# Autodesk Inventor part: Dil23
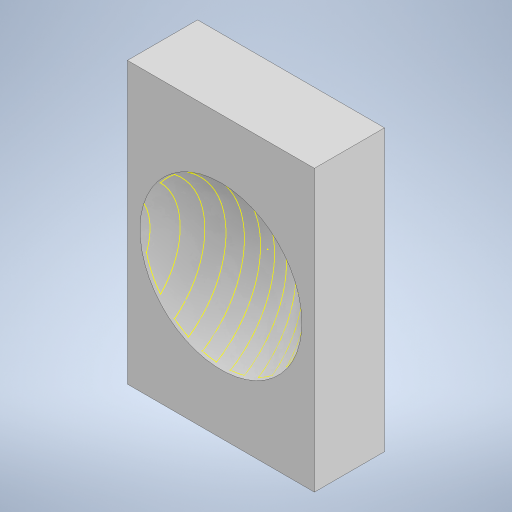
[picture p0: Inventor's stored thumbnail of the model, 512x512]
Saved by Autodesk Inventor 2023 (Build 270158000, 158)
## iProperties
Created: 2023-08
Part Number: Dil23
Material: Všeobecné
Document SubType Name: Modeling
Designer: KSR-Student_2
Density: 1 g/cm^3
Appearance: Výchozí
Author: KSR-Student_2
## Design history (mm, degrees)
sketch "Náčrt1"
  geometry: L1 (0, 0)-(400, 0); L2 (400, 0)-(400, -600); L3 (400, -600)-(0, -600); L4 (0, -600)-(0, 0)
  constraints: 8 end point, 2 parallel, 1 horizontal, 1 perpendicular
  dimensions: "d0" = 400 distance of L2.end L3.end; "d1" = 600 distance of L1.end L2.end
extrude "Vysunutí1" new body sketch "Náčrt1" distance "d2" = 150; taper "d3" = 0 deg
node "Pracovní rovina1"
sketch "Náčrt2"
  geometry: L1 (-150, 0)-(-150, 600) reference; L2 (-150, 600)-(-150, 0) reference; L3 (-150, 300)-(-50, 300); L4 (-150, 300)-(-150, 473.205); A1 r 200 centre (-250, 300) between (-50, 300) and (-150, 473.205); 3 further points
  constraints: 4 end point, 2 midpoint, 2 point on circle, 1 centre point, 1 perpendicular, 1 point on line
  dimensions: "d5" = 400 diameter of A1; "d6" = 100 distance from line of L1 A1.centre; "d7" = 100 distance of point (-150, 300) A1.centre
revolve "Rotace1" sketch "Náčrt2" stored, may be unused: angle "d8" = 90 deg
node "Pracovní rovina2"
sketch "Náčrt3"
  geometry: L1 (95, -166.303)-(95, -433.697); L2 (185, -130.663)-(185, -469.337); L3 (155, -136.064)-(155, -463.936); L4 (125, -147.439)-(125, -452.561); L5 (65, -196.68)-(65, -403.32); L6 (35, -249.41)-(35, -340.927); L7 (365, -248.657)-(365, -340.927); L8 (335, -196.68)-(335, -403.32); L9 (305, -166.303)-(305, -433.697); L10 (275, -147.439)-(275, -452.561); L11 (245, -136.064)-(245, -463.936); L12 (215, -130.663)-(215, -469.337); A1 r 170 centre (200, -300) between (35, -340.927) and (65, -403.32); A2 r 170 centre (200, -300) between (95, -433.697) and (125, -452.561); A3 r 170 centre (200, -300) between (155, -463.936) and (185, -469.337); A4 r 170 centre (200, -300) between (95, -166.303) and (65, -196.68); A5 r 170 centre (200, -300) between (200, -130) and (185, -130.663); A6 r 170 centre (200, -300) between (155, -136.064) and (125, -147.439); A7 r 170 centre (200, -300) between (275, -147.439) and (245, -136.064); A8 r 170 centre (200, -300) between (215, -130.663) and (200, -130); A9 r 170 centre (200, -300) between (335, -403.32) and (365, -340.927); A10 r 170 centre (200, -300) between (275, -452.561) and (305, -433.697); A11 r 170 centre (200, -300) between (215, -469.337) and (245, -463.936); A12 r 170 centre (200, -300) between (335, -196.68) and (305, -166.303); 1 further point
  constraints: 24 end point, 24 point on circle, 12 centre point, 6 vertical
  dimensions: "d14" = 30 distance between parallel lines of L2 L3; "d15" = 30 distance between parallel lines of L4 L3; "d16" = 30 distance between parallel lines of L1 L4; "d18" = 30 distance between parallel lines of L5 L1; "d19" = 30 distance between parallel lines of L6 L5; "d21" = 170 radius of A7; "d22" = 170 radius of A12; "d23" = 170 radius of A9; "d24" = 170 radius of A10; "d25" = 170 radius of A11; "d26" = 170 radius of A8
sketch "3D náčrt4"
  node "Promítnout na plochu4"
sketch "3D náčrt6"
  node "Promítnout na plochu5"
node "Těleso1"
other parameters: "d20" = 346.41016
